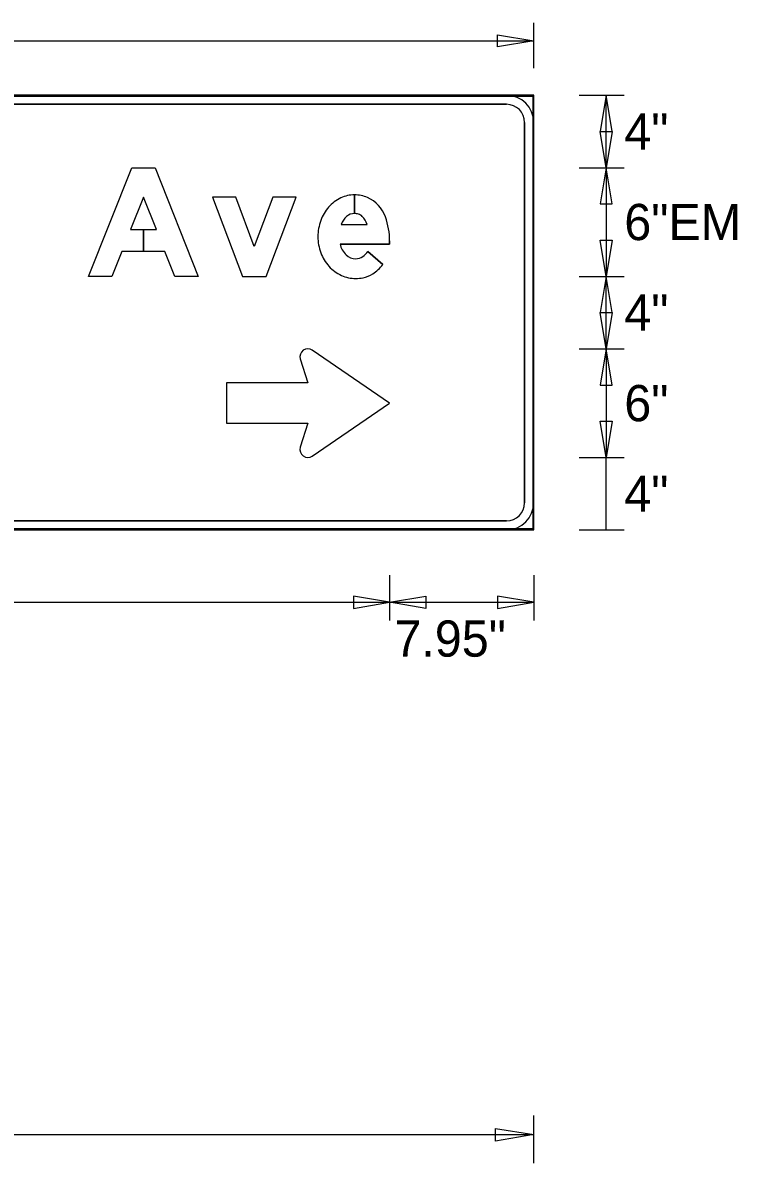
# Model space of a CAD drawing. Extents: x 1374 to 1480, y 568 to 638.
# Drawn here: x 1421.51 to 1424.79, y 632.21 to 637.45 of the extents above; entities that cross this region are included whole.
import ezdxf

# ---------------------------------------------------------------- set-up
doc = ezdxf.new("R2010")
doc.units = 0
for name, color, linetype in [('GSBWFill', 7, 'Continuous'), ('GSColorFill', 7, 'Continuous'), ('GSDims', 7, 'Continuous'), ('GSOutline', 7, 'Continuous')]:
    doc.layers.add(name, color=color, linetype=linetype)

msp = doc.modelspace()

# ---------------------------------------------------------------- linework, layer by layer
at = {"layer": 'GSBWFill'}
for p, q in [((1423.8581, 637.1193), (1414.8581, 637.1193)), ((1423.7331, 637.1193), (1414.9831, 637.1193)), ((1423.8581, 635.1193), (1423.8581, 637.1193)), ((1414.9831, 637.0776), (1423.7331, 637.0776)), ((1423.8165, 636.9943), (1423.8165, 635.2443)), ((1423.8581, 635.2443), (1423.8581, 636.9943)), ((1423.0341, 636.661), (1423.0341, 636.5747)), ((1423.0342, 636.5747), (1423.0342, 636.661)), ((1422.9731, 636.5246), (1423.0916, 636.5246)), ((1423.0956, 636.4007), (1423.164, 636.3401)), ((1423.7331, 635.161), (1414.9835, 635.161)), ((1414.8581, 635.1193), (1423.8581, 635.1193)), ((1414.9835, 635.1193), (1423.7331, 635.1193))]:
    msp.add_line(p, q, dxfattribs=at)
for points in [[(1422.0631, 636.501), (1422.0631, 636.401), (1421.9639, 636.401), (1421.9182, 636.286), (1421.8106, 636.286), (1422.0093, 636.786), (1422.1169, 636.786), (1422.3156, 636.286), (1422.208, 636.286), (1422.1623, 636.401), (1422.0632, 636.401), (1422.0632, 636.501), (1422.1226, 636.501), (1422.0631, 636.6506), (1422.0037, 636.501)], [(1422.4875, 636.651), (1422.3806, 636.651), (1422.5181, 636.286), (1422.6281, 636.286), (1422.7656, 636.651), (1422.6588, 636.651), (1422.5731, 636.4236)]]:
    msp.add_lwpolyline(points, close=True, dxfattribs=at)
for points in [[(1423.1956, 636.4489), (1423.1956, 636.4346), (1422.9674, 636.4346)], [(1422.8397, 635.4589), (1423.1956, 635.7026), (1422.8397, 635.9463)], [(1422.7848, 635.906), (1422.8188, 635.7954), (1422.4456, 635.7954)], [(1422.4456, 635.7954), (1422.4456, 635.6099), (1422.8188, 635.6099), (1422.7848, 635.4993)]]:
    msp.add_lwpolyline(points, dxfattribs=at)
for centre, radius, start, end in [((1423.7331, 636.9943), 0.125, 0, 90), ((1423.7331, 636.9943), 0.0833, 0, 90), ((1423.0443, 636.4914), 0.1719, 115.3224, 138.8015), ((1423.0341, 636.5129), 0.1481, 90, 115.3224), ((1423.0341, 636.5129), 0.1481, 66.2413, 89.9903), ((1423.0304, 636.507), 0.155, 19.9901, 65.8469), ((1423.0602, 636.4775), 0.193, 138.8015, 160.0695), ((1423.0341, 636.5168), 0.058, 90, 129.2086), ((1423.0341, 636.5075), 0.0672, 74.2341, 89.9787), ((1423.0422, 636.5361), 0.0375, 43.3306, 74.2341), ((1423.085, 636.4685), 0.2194, 160.0695, 180), ((1423.0483, 636.5017), 0.0786, 130.2868, 163.0777), ((1422.9975, 636.4939), 0.099, 18.0656, 43.3306), ((1422.8706, 636.4489), 0.325, 0, 19.9901), ((1423.0785, 636.4685), 0.2129, 180, 200.5021), ((1423.0635, 636.4558), 0.0984, 192.4467, 226.2893), ((1423.0594, 636.4613), 0.1925, 200.5021, 222.0738), ((1423.0403, 636.4319), 0.0651, 226.5476, 269.2365), ((1423.0345, 636.4385), 0.0718, 273.8929, 328.2838), ((1423.0472, 636.4503), 0.1761, 222.0738, 245.3524), ((1423.0174, 636.455), 0.1862, 302.591, 321.9228), ((1423.0394, 636.4333), 0.1573, 245.3524, 270), ((1423.0394, 636.4333), 0.1573, 270, 282.4743), ((1423.0437, 636.4139), 0.1375, 282.4743, 302.591), ((1422.8193, 635.9166), 0.0361, 55.6003, 197.0573), ((1422.8193, 635.4887), 0.0361, 162.9427, 304.3997), ((1423.7331, 635.2443), 0.125, 270, 0), ((1423.7331, 635.2443), 0.0833, 270, 0)]:
    msp.add_arc(centre, radius, start, end, dxfattribs=at)
at = {"layer": 'GSColorFill'}
for p, q in [((1423.8581, 637.1193), (1414.8581, 637.1193)), ((1423.8581, 637.1193), (1414.8581, 637.1193)), ((1414.8623, 637.1151), (1423.854, 637.1151)), ((1423.7331, 637.1193), (1414.9831, 637.1193)), ((1423.854, 637.1151), (1423.854, 635.1235)), ((1423.8581, 635.1193), (1423.8581, 637.1193)), ((1423.8581, 635.1193), (1423.8581, 637.1193)), ((1414.9831, 637.0776), (1423.7331, 637.0776)), ((1423.8165, 636.9943), (1423.8165, 635.2443)), ((1423.8581, 635.2443), (1423.8581, 636.9943)), ((1423.0341, 636.661), (1423.0341, 636.5747)), ((1423.0342, 636.5747), (1423.0342, 636.661)), ((1422.9731, 636.5246), (1423.0916, 636.5246)), ((1423.0956, 636.4007), (1423.164, 636.3401)), ((1423.7331, 635.161), (1414.9835, 635.161)), ((1423.854, 635.1235), (1414.8581, 635.1235)), ((1414.8581, 635.1193), (1423.8581, 635.1193)), ((1414.8581, 635.1193), (1423.8581, 635.1193)), ((1414.9835, 635.1193), (1423.7331, 635.1193))]:
    msp.add_line(p, q, dxfattribs=at)
for points in [[(1422.0631, 636.501), (1422.0631, 636.401), (1421.9639, 636.401), (1421.9182, 636.286), (1421.8106, 636.286), (1422.0093, 636.786), (1422.1169, 636.786), (1422.3156, 636.286), (1422.208, 636.286), (1422.1623, 636.401), (1422.0632, 636.401), (1422.0632, 636.501), (1422.1226, 636.501), (1422.0631, 636.6506), (1422.0037, 636.501)], [(1422.4875, 636.651), (1422.3806, 636.651), (1422.5181, 636.286), (1422.6281, 636.286), (1422.7656, 636.651), (1422.6588, 636.651), (1422.5731, 636.4236)]]:
    msp.add_lwpolyline(points, close=True, dxfattribs=at)
for points in [[(1423.1956, 636.4489), (1423.1956, 636.4346), (1422.9674, 636.4346)], [(1422.8397, 635.4589), (1423.1956, 635.7026), (1422.8397, 635.9463)], [(1422.7848, 635.906), (1422.8188, 635.7954), (1422.4456, 635.7954)], [(1422.4456, 635.7954), (1422.4456, 635.6099), (1422.8188, 635.6099), (1422.7848, 635.4993)]]:
    msp.add_lwpolyline(points, dxfattribs=at)
for centre, radius, start, end in [((1423.7331, 636.9943), 0.125, 0, 90), ((1423.7331, 636.9943), 0.0833, 0, 90), ((1423.0443, 636.4914), 0.1719, 115.3224, 138.8015), ((1423.0341, 636.5129), 0.1481, 90, 115.3224), ((1423.0341, 636.5129), 0.1481, 66.2413, 89.9903), ((1423.0304, 636.507), 0.155, 19.9901, 65.8469), ((1423.0602, 636.4775), 0.193, 138.8015, 160.0695), ((1423.0341, 636.5168), 0.058, 90, 129.2086), ((1423.0341, 636.5075), 0.0672, 74.2341, 89.9787), ((1423.0422, 636.5361), 0.0375, 43.3306, 74.2341), ((1423.085, 636.4685), 0.2194, 160.0695, 180), ((1423.0483, 636.5017), 0.0786, 130.2868, 163.0777), ((1422.9975, 636.4939), 0.099, 18.0656, 43.3306), ((1422.8706, 636.4489), 0.325, 0, 19.9901), ((1423.0785, 636.4685), 0.2129, 180, 200.5021), ((1423.0635, 636.4558), 0.0984, 192.4467, 226.2893), ((1423.0594, 636.4613), 0.1925, 200.5021, 222.0738), ((1423.0403, 636.4319), 0.0651, 226.5476, 269.2365), ((1423.0345, 636.4385), 0.0718, 273.8929, 328.2838), ((1423.0472, 636.4503), 0.1761, 222.0738, 245.3524), ((1423.0174, 636.455), 0.1862, 302.591, 321.9228), ((1423.0394, 636.4333), 0.1573, 245.3524, 270), ((1423.0394, 636.4333), 0.1573, 270, 282.4743), ((1423.0437, 636.4139), 0.1375, 282.4743, 302.591), ((1422.8193, 635.9166), 0.0361, 55.6003, 197.0573), ((1422.8193, 635.4887), 0.0361, 162.9427, 304.3997), ((1423.7331, 635.2443), 0.125, 270, 0), ((1423.7331, 635.2443), 0.0833, 270, 0)]:
    msp.add_arc(centre, radius, start, end, dxfattribs=at)
at = {"layer": 'GSDims'}
for p, q in [((1423.8581, 637.2443), (1423.8581, 637.4526)), ((1414.8581, 637.3693), (1423.8581, 637.3693)), ((1423.8581, 637.2443), (1423.8581, 637.2443)), ((1424.0665, 637.1193), (1424.2748, 637.1193)), ((1424.0665, 637.1193), (1424.0665, 637.1193)), ((1424.1915, 636.786), (1424.1915, 637.1193)), ((1424.0665, 636.786), (1424.2748, 636.786)), ((1424.0665, 636.786), (1424.2748, 636.786)), ((1424.1915, 636.786), (1424.1915, 636.286)), ((1424.0665, 636.286), (1424.2748, 636.286)), ((1424.0665, 636.286), (1424.2748, 636.286)), ((1424.1915, 635.9526), (1424.1915, 636.286)), ((1424.0665, 635.9526), (1424.2748, 635.9526)), ((1424.0665, 635.9526), (1424.2748, 635.9526)), ((1424.1915, 635.9526), (1424.1915, 635.4526)), ((1424.0665, 635.4526), (1424.2748, 635.4526)), ((1424.0665, 635.4526), (1424.2748, 635.4526)), ((1424.1915, 635.1193), (1424.1915, 635.4526)), ((1424.0665, 635.1193), (1424.2748, 635.1193)), ((1424.0665, 635.1193), (1424.0665, 635.1193)), ((1423.1956, 634.911), (1423.1956, 634.7026)), ((1423.1956, 634.911), (1423.1956, 634.7026)), ((1423.8581, 634.911), (1423.8581, 634.7026)), ((1423.8581, 634.911), (1423.8581, 634.7026)), ((1415.5206, 634.786), (1423.1956, 634.786)), ((1423.1956, 634.786), (1423.8581, 634.786)), ((1423.8581, 632.2052), (1423.8581, 632.424)), ((1414.8581, 632.3365), (1423.8581, 632.3365)), ((1423.8581, 632.2052), (1423.8581, 632.2052))]:
    msp.add_line(p, q, dxfattribs=at)
for points in [[(1423.8581, 637.3693), (1423.6915, 637.3415), (1423.6915, 637.3971)], [(1424.1915, 637.1193), (1424.1637, 636.9526), (1424.2192, 636.9526)], [(1424.1915, 636.786), (1424.1637, 636.9526), (1424.2192, 636.9526)], [(1424.1915, 636.786), (1424.1637, 636.6193), (1424.2192, 636.6193)], [(1424.1915, 636.286), (1424.1637, 636.4526), (1424.2192, 636.4526)], [(1424.1915, 636.286), (1424.1637, 636.1193), (1424.2192, 636.1193)], [(1424.1915, 635.9526), (1424.1637, 636.1193), (1424.2192, 636.1193)], [(1424.1915, 635.9526), (1424.1637, 635.786), (1424.2192, 635.786)], [(1424.1915, 635.4526), (1424.1637, 635.6193), (1424.2192, 635.6193)], [(1423.1956, 634.786), (1423.029, 634.8138), (1423.029, 634.7582)], [(1423.1956, 634.786), (1423.3623, 634.8138), (1423.3623, 634.7582)], [(1423.8581, 634.786), (1423.6915, 634.8138), (1423.6915, 634.7582)], [(1423.8581, 632.3365), (1423.6831, 632.3073), (1423.6831, 632.3656)]]:
    msp.add_lwpolyline(points, close=True, dxfattribs=at)
at = {"layer": 'GSOutline'}
for p, q in [((1423.8581, 637.1193), (1414.8581, 637.1193)), ((1423.7331, 637.1193), (1414.9831, 637.1193)), ((1423.8581, 635.1193), (1423.8581, 637.1193)), ((1423.7331, 637.0776), (1414.9831, 637.0776)), ((1423.8165, 635.2443), (1423.8165, 636.9943)), ((1423.8581, 635.2443), (1423.8581, 636.9943)), ((1422.9731, 636.5246), (1423.0916, 636.5246)), ((1423.164, 636.3401), (1423.0956, 636.4007)), ((1414.9831, 635.161), (1423.7331, 635.161)), ((1414.8581, 635.1193), (1423.8581, 635.1193)), ((1414.9831, 635.1193), (1423.7331, 635.1193))]:
    msp.add_line(p, q, dxfattribs=at)
for points in [[(1422.1623, 636.401), (1421.9639, 636.401), (1421.9182, 636.286), (1421.8106, 636.286), (1422.0093, 636.786), (1422.1169, 636.786), (1422.3156, 636.286), (1422.208, 636.286)], [(1422.0037, 636.501), (1422.1226, 636.501), (1422.0631, 636.6506)], [(1422.4875, 636.651), (1422.3806, 636.651), (1422.5181, 636.286), (1422.6281, 636.286), (1422.7656, 636.651), (1422.6588, 636.651), (1422.5731, 636.4236)]]:
    msp.add_lwpolyline(points, close=True, dxfattribs=at)
for points in [[(1422.9674, 636.4346), (1423.1956, 636.4346), (1423.1956, 636.4489)], [(1422.8397, 635.4589), (1423.1956, 635.7026), (1422.8397, 635.9463)], [(1422.7848, 635.906), (1422.8188, 635.7954), (1422.4456, 635.7954)], [(1422.4456, 635.7954), (1422.4456, 635.6099), (1422.8188, 635.6099), (1422.7848, 635.4993)]]:
    msp.add_lwpolyline(points, dxfattribs=at)
for centre, radius, start, end in [((1423.7331, 636.9943), 0.125, 0, 90), ((1423.7331, 636.9943), 0.0833, 0, 90), ((1423.0443, 636.4914), 0.1719, 115.3224, 138.8015), ((1423.0341, 636.5129), 0.1481, 90, 115.3224), ((1423.0341, 636.5129), 0.1481, 66.2413, 90), ((1423.0304, 636.507), 0.155, 19.9901, 65.8469), ((1423.0602, 636.4775), 0.193, 138.8015, 160.0695), ((1423.0341, 636.5168), 0.058, 90, 129.2086), ((1423.0341, 636.5075), 0.0672, 74.2341, 90), ((1423.0422, 636.5361), 0.0375, 43.3306, 74.2341), ((1423.085, 636.4685), 0.2194, 160.0695, 180), ((1423.0483, 636.5017), 0.0786, 130.2868, 163.0777), ((1422.9975, 636.4939), 0.099, 18.0656, 43.3306), ((1422.8706, 636.4489), 0.325, 0, 19.9901), ((1423.0785, 636.4685), 0.2129, 180, 200.5021), ((1423.0635, 636.4558), 0.0984, 192.4467, 226.2893), ((1423.0594, 636.4613), 0.1925, 200.5021, 222.0738), ((1423.0403, 636.4319), 0.0651, 226.5476, 269.2365), ((1423.0345, 636.4385), 0.0718, 273.8929, 328.2838), ((1423.0472, 636.4503), 0.1761, 222.0738, 245.3524), ((1423.0174, 636.455), 0.1862, 302.591, 321.9228), ((1423.0394, 636.4333), 0.1573, 245.3524, 270), ((1423.0394, 636.4333), 0.1573, 270, 282.4743), ((1423.0437, 636.4139), 0.1375, 282.4743, 302.591), ((1422.8193, 635.9166), 0.0361, 55.6003, 197.0573), ((1422.8193, 635.4887), 0.0361, 162.9427, 304.3997), ((1423.7331, 635.2443), 0.125, 270, 0), ((1423.7331, 635.2443), 0.0833, 270, 0)]:
    msp.add_arc(centre, radius, start, end, dxfattribs=at)

# ---------------------------------------------------------------- texts
at = {"layer": 'GSDims'}
for s, p in [('4"', (1424.2748, 636.8693)), ('6"EM', (1424.2748, 636.4526)), ('4"', (1424.2748, 636.036)), ('6"', (1424.2748, 635.6193)), ('4"', (1424.2748, 635.2026)), ('7.95"', (1423.2174, 634.536))]:
    msp.add_text(s, height=0.16667, dxfattribs=at).set_placement(p)

doc.saveas('drawing.dxf')
